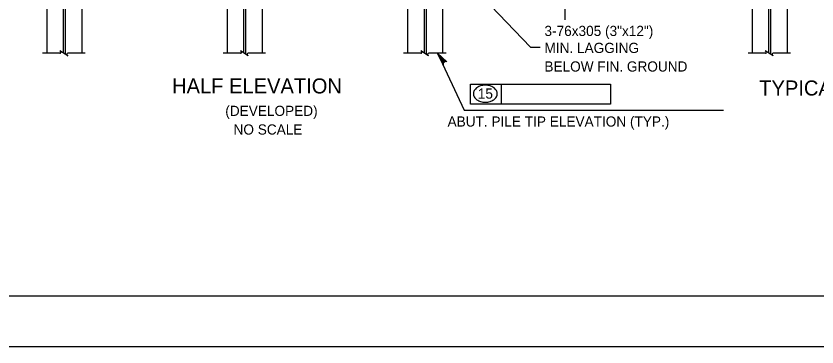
# Model space of a CAD drawing. Extents: x 635440 to 640306, y 296653 to 298484.
# Drawn here: x 639457.3 to 639693.2, y 296653.5 to 296751 of the extents above; entities that cross this region are included whole.
import ezdxf

# ---------------------------------------------------------------- set-up
doc = ezdxf.new("R2010")
doc.units = 0
for name, color, linetype in [('2', 7, 'Continuous'), ('3', 7, 'Continuous'), ('4', 7, 'Continuous'), ('5', 7, 'Continuous'), ('8', 7, 'Continuous'), ('PLT-BNDY', 7, 'Continuous')]:
    doc.layers.add(name, color=color, linetype=linetype)

msp = doc.modelspace()

# ---------------------------------------------------------------- linework, layer by layer
at = {"layer": '2'}
msp.add_line((640102.46, 296668.46), (639316.46, 296668.46), dxfattribs=at)
at = {"layer": '3'}
for p, q in [((639466.31, 296786.03), (639466.31, 296740.25)), ((639476.64, 296784.63), (639476.64, 296739.98)), ((639519.46, 296784.63), (639519.46, 296740.25)), ((639529.79, 296784.63), (639529.79, 296739.98)), ((639572.61, 296784.63), (639572.61, 296740.31)), ((639582.94, 296784.63), (639582.94, 296740.04)), ((639674.1, 296784.63), (639674.1, 296739.99)), ((639684.43, 296786.03), (639684.43, 296740.26))]:
    msp.add_line(p, q, dxfattribs=at)
at = {"layer": '4'}
for p, q in [((639618.98, 296850.77), (639618.98, 296749.87)), ((639586.54, 296765.12), (639608.82, 296741.76)), ((639608.82, 296741.76), (639611.66, 296741.76)), ((639591.14, 296730.91), (639632.35, 296730.91)), ((639591.14, 296725.01), (639591.14, 296730.91)), ((639600.31, 296725.01), (639600.31, 296730.91)), ((639632.35, 296730.91), (639632.35, 296725.01)), ((639589.31, 296723.18), (639665.64, 296723.18)), ((639632.35, 296725.01), (639591.14, 296725.01))]:
    msp.add_line(p, q, dxfattribs=at)
for points in [[(639581.42, 296739.98), (639589.31, 296723.18)], [(639581.42, 296739.98), (639584.22, 296737.42), (639583.88, 296737.53), (639583.6, 296737.49), (639583.37, 296737.38), (639583.2, 296737.19), (639583.08, 296736.93), (639583.1, 296736.58), (639581.42, 296739.98), (639583.08, 296736.93), (639583.2, 296737.19), (639581.42, 296739.98), (639583.37, 296737.38), (639583.6, 296737.49), (639581.42, 296739.98), (639583.88, 296737.53)]]:
    msp.add_lwpolyline(points, dxfattribs=at)
msp.add_lwpolyline([(639581.42, 296739.98), (639583, 296737.47), (639583.39, 296737.76)], close=True, dxfattribs=at)
for centre, radius, start, end in [((639595.18, 296726.87), 3.66, 106.5358, 125.6316), ((639595.52, 296725.71), 4.87, 90, 106.5358), ((639595.52, 296725.71), 4.87, 73.4642, 90), ((639595.86, 296726.87), 3.66, 54.3684, 73.4642), ((639593.84, 296728.07), 1.83, 149.9767, 180), ((639593.84, 296728.07), 1.83, 180, 210.0233), ((639594.65, 296727.6), 2.76, 125.6316, 149.9767), ((639596.39, 296727.6), 2.76, 30.0233, 54.3684), ((639597.2, 296728.07), 1.83, 0, 30.0233), ((639597.2, 296728.07), 1.83, 329.9767, 0), ((639594.65, 296728.53), 2.76, 210.0233, 234.3684), ((639595.18, 296729.27), 3.66, 234.3684, 253.4642), ((639595.52, 296730.43), 4.87, 253.4642, 270), ((639595.52, 296730.43), 4.87, 270, 286.5358), ((639595.86, 296729.27), 3.66, 286.5358, 305.6316), ((639596.39, 296728.53), 2.76, 305.6316, 329.9767)]:
    msp.add_arc(centre, radius, start, end, dxfattribs=at)
at = {"layer": '8'}
for p, q in [((639471.18, 296830.96), (639471.18, 296740.09)), ((639471.77, 296830.96), (639471.77, 296739.72)), ((639524.33, 296830.96), (639524.33, 296740.09)), ((639524.92, 296830.96), (639524.92, 296739.72)), ((639577.48, 296830.96), (639577.48, 296740.09)), ((639578.07, 296830.96), (639578.07, 296739.72)), ((639678.97, 296830.96), (639678.97, 296740.09)), ((639679.56, 296830.96), (639679.56, 296739.72)), ((639470.21, 296739.98), (639465.11, 296739.98)), ((639477.65, 296739.98), (639472.54, 296739.98)), ((639523.37, 296739.98), (639518.27, 296739.98)), ((639530.8, 296739.98), (639525.7, 296739.98)), ((639576.52, 296739.98), (639571.42, 296739.98)), ((639583.95, 296739.98), (639578.85, 296739.98)), ((639678.01, 296739.98), (639672.91, 296739.98)), ((639685.44, 296739.98), (639680.34, 296739.98))]:
    msp.add_line(p, q, dxfattribs=at)
for points in [[(639472.37, 296739.34), (639472.52, 296739.25), (639470.21, 296740.7), (639470.36, 296740.6)], [(639525.53, 296739.34), (639525.67, 296739.25), (639523.36, 296740.7), (639523.52, 296740.6)], [(639578.68, 296739.34), (639578.82, 296739.25), (639576.51, 296740.7), (639576.67, 296740.6)], [(639680.17, 296739.34), (639680.31, 296739.25), (639678, 296740.7), (639678.16, 296740.6)]]:
    msp.add_lwpolyline(points, dxfattribs=at)
for centre, start, end in [((639470.18, 296740.32), 275.3286, 57.8672), ((639472.55, 296739.63), 90, 240), ((639523.33, 296740.32), 275.3286, 57.8672), ((639525.7, 296739.63), 90, 240), ((639576.49, 296740.32), 275.3286, 57.8672), ((639578.85, 296739.63), 90, 240), ((639677.98, 296740.32), 275.3286, 57.8672), ((639680.34, 296739.63), 90, 240)]:
    msp.add_arc(centre, 0.341, start, end, dxfattribs=at)
at = {"layer": 'PLT-BNDY'}
msp.add_lwpolyline([(639276.46, 297247.46), (640117.46, 297247.46), (640117.46, 296653.46), (639276.46, 296653.46)], close=True, dxfattribs=at)

# ---------------------------------------------------------------- texts
at = {"layer": '4'}
for s, height, p in [('BELOW FIN. GROUND', 3.0001, (639612.92, 296734.59)), ('HALF ELEVATION', 4.4294, (639503.24, 296728.15)), ('TYPICAL WING ELEVATION', 4.4294, (639676.21, 296727.54)), ('15', 3, (639593.3, 296726.61)), ('(DEVELOPED)', 3.0001, (639518.92, 296721.52)), ('ABUT. PILE TIP ELEVATION (TYP.)', 3.0001, (639584.4, 296718.38)), ('NO SCALE', 3, (639521.35, 296716.03))]:
    msp.add_text(s, height=height, dxfattribs=at).set_placement(p)
at = {"layer": '5'}
for s, p in [('3-76x305 (3"x12")', (639612.94, 296745.07)), ('MIN. LAGGING', (639612.94, 296740.07))]:
    msp.add_text(s, height=3.0001, dxfattribs=at).set_placement(p)

doc.saveas('drawing.dxf')
